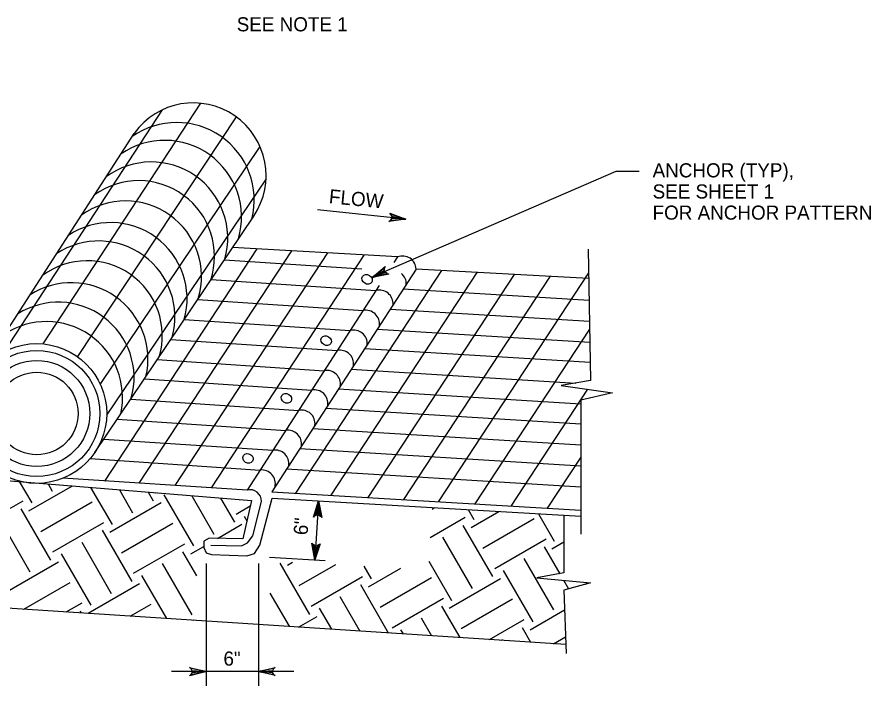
# Model space of a CAD drawing. Extents: x 636462 to 638208, y 299350 to 300538.
# Drawn here: x 636572.1 to 636753.7, y 299625.6 to 299768 of the extents above; entities that cross this region are included whole.
import ezdxf

# ---------------------------------------------------------------- set-up
doc = ezdxf.new("R2010")
doc.units = 0
doc.layers.add('Default', color=7, linetype='Continuous')

msp = doc.modelspace()

# ---------------------------------------------------------------- linework, layer by layer
at = {"layer": 'Default'}
for p, q in [((636577.62, 299698.4), (636611.18, 299749.62)), ((636602.95, 299748.21), (636569.31, 299696.75)), ((636618.69, 299746.73), (636584.88, 299695.7)), ((636563.74, 299691.65), (636596.98, 299743.21)), ((636589.76, 299689.79), (636623.74, 299740.43)), ((636647.45, 299712.59), (636699.52, 299735.16)), ((636699.52, 299735.16), (636704.42, 299735.16)), ((636625.02, 299733.53), (636591.11, 299683.2)), ((636588.59, 299675.29), (636622.41, 299725.61)), ((636623.04, 299718.61), (636590.67, 299669.22)), ((636630.4, 299718.19), (636597.99, 299668.75)), ((636638.07, 299717.76), (636605.62, 299668.25)), ((636653.02, 299716.91), (636617.9, 299718.9)), ((636645.85, 299717.32), (636613.36, 299667.75)), ((636616.16, 299716.31), (636645.39, 299714.35)), ((636662.37, 299714.01), (636631.31, 299666.62)), ((636669.89, 299713.61), (636638.8, 299666.18)), ((636677.82, 299713.19), (636646.7, 299665.71)), ((636685.43, 299712.79), (636654.27, 299665.25)), ((636693.62, 299713.56), (636661.67, 299664.81)), ((636613.32, 299712.09), (636648.39, 299709.74)), ((636649.11, 299710.86), (636621, 299667.25)), ((636654.22, 299710.11), (636693.73, 299707.71)), ((636610.48, 299707.86), (636645.66, 299705.5)), ((636651.42, 299705.79), (636693.81, 299703.21)), ((636607.62, 299703.61), (636642.91, 299701.24)), ((636648.64, 299701.51), (636693.89, 299698.75)), ((636693.84, 299701.52), (636669.47, 299664.35)), ((636604.77, 299699.36), (636640.17, 299696.98)), ((636646.02, 299697.45), (636693.97, 299694.53)), ((636601.89, 299695.08), (636637.4, 299692.69)), ((636643.12, 299692.99), (636690.93, 299690.08)), ((636599.13, 299690.98), (636634.75, 299688.58)), ((636640.42, 299688.82), (636691.97, 299685.68)), ((636693.42, 299688.76), (636677.13, 299663.89)), ((636596.23, 299686.66), (636631.96, 299684.26)), ((636637.75, 299684.7), (636691.97, 299681.4)), ((636593.35, 299682.38), (636629.2, 299679.97)), ((636634.97, 299680.41), (636691.97, 299676.94)), ((636590.52, 299678.16), (636626.47, 299675.75)), ((636632.19, 299676.12), (636691.97, 299672.48)), ((636691.97, 299674.29), (636684.85, 299663.43)), ((636587.6, 299673.98), (636623.77, 299671.55)), ((636629.37, 299671.78), (636691.97, 299667.96)), ((636572.53, 299669.11), (636575.17, 299664.54)), ((636578.65, 299668.61), (636579.54, 299667.07)), ((636621, 299667.25), (636581.82, 299669.8)), ((636574.58, 299662.85), (636583.82, 299668.18)), ((636587.7, 299667.86), (636592.27, 299659.96)), ((636593.82, 299667.36), (636596.63, 299662.48)), ((636599.93, 299666.86), (636601, 299665)), ((636562.4, 299658.73), (636573.32, 299665.03)), ((636601.46, 299666.72), (636601.47, 299666.73)), ((636603.27, 299666.31), (636609.57, 299655.39)), ((636609.22, 299666.09), (636613.94, 299657.91)), ((636615.33, 299665.59), (636618.31, 299660.43)), ((636636.18, 299664.97), (636635.43, 299652.42)), ((636572.86, 299663.31), (636579.17, 299652.39)), ((636577.11, 299658.48), (636588.02, 299664.79)), ((636591.76, 299658.31), (636602.68, 299664.62)), ((636618.64, 299662.18), (636621.65, 299663.92)), ((636660.34, 299663.26), (636660.82, 299663.54)), ((636620.36, 299661.72), (636620.94, 299660.72)), ((636659.97, 299657.23), (636667.38, 299661.5)), ((636668, 299663.12), (636669.22, 299661.01)), ((636668.64, 299659.32), (636674.57, 299662.74)), ((636682.95, 299662.26), (636686.32, 299656.43)), ((636568.5, 299660.79), (636574.8, 299649.87)), ((636579.63, 299654.12), (636590.54, 299660.42)), ((636594.28, 299653.94), (636605.2, 299660.25)), ((636614.71, 299657), (636619.9, 299660)), ((636666.92, 299659.78), (636673.22, 299648.86)), ((636671.16, 299654.95), (636682.08, 299661.25)), ((636590.17, 299658.75), (636596.47, 299647.83)), ((636585.8, 299656.22), (636592.1, 299645.3)), ((636596.8, 299649.58), (636607.72, 299655.88)), ((636662.55, 299657.26), (636668.85, 299646.34)), ((636673.68, 299650.58), (636684.6, 299656.89)), ((636685.81, 299654.78), (636688.34, 299656.24)), ((636607.26, 299654.16), (636610.23, 299649.01)), ((636608.99, 299653.7), (636611.77, 299655.31)), ((636684.22, 299655.21), (636687.52, 299649.49)), ((636581.43, 299653.7), (636587.73, 299642.78)), ((636625.77, 299653), (636637.61, 299652.29)), ((636679.85, 299652.69), (636686.16, 299641.77)), ((636569.92, 299645.71), (636580.84, 299652.01)), ((636602.9, 299651.64), (636609.2, 299640.72)), ((636612.26, 299651.65), (636612.26, 299625.6)), ((636623.44, 299651.65), (636623.44, 299625.6)), ((636627.98, 299651.76), (636634.29, 299640.84)), ((636629.58, 299651.33), (636630.66, 299651.95)), ((636632.1, 299646.96), (636639.88, 299651.45)), ((636645.82, 299651.12), (636647.39, 299648.4)), ((636646.8, 299646.71), (636653.69, 299650.69)), ((636659.66, 299652.17), (636664.48, 299643.82)), ((636598.53, 299649.12), (636603.82, 299639.95)), ((636634.62, 299642.59), (636645.54, 299648.89)), ((636649.32, 299642.34), (636660.24, 299648.65)), ((636675.48, 299650.17), (636681.79, 299639.25)), ((636688.34, 299650.41), (636688.34, 299650.41)), ((636573.47, 299641.93), (636583.37, 299647.64)), ((636587.15, 299641.09), (636598.07, 299647.39)), ((636645.08, 299647.17), (636651.02, 299636.88)), ((636663.98, 299642.17), (636674.9, 299648.48)), ((636688.33, 299648.08), (636689.37, 299646.29)), ((636693, 299647.28), (636693.57, 299647.61)), ((636625.85, 299645.36), (636629.92, 299638.32)), ((636582.53, 299641.34), (636585.89, 299643.27)), ((636640.71, 299644.65), (636644.97, 299637.27)), ((636651.84, 299637.98), (636662.76, 299644.28)), ((636666.5, 299637.8), (636677.42, 299644.11)), ((636585.43, 299641.55), (636585.67, 299641.13)), ((636596.13, 299640.45), (636600.59, 299643.03)), ((636636.34, 299642.13), (636638.92, 299637.67)), ((636662.38, 299642.61), (636666.26, 299635.89)), ((636681.2, 299637.56), (636688.5, 299641.77)), ((636609.57, 299639.58), (636609.74, 299639.68)), ((636631.93, 299638.12), (636635.88, 299640.41)), ((636658.01, 299640.08), (636660.21, 299636.28)), ((636672.56, 299635.48), (636679.94, 299639.74)), ((636679.48, 299638.02), (636681.27, 299634.91)), ((636653.65, 299637.56), (636654.16, 299636.68)), ((636686.15, 299634.59), (636688.72, 299636.08)), ((636675.11, 299635.5), (636675.22, 299635.3))]:
    msp.add_line(p, q, dxfattribs=at)
for points in [[(636654.73, 299724.96), (636635.99, 299726.96)], [(636651.59, 299725.97), (636651.35, 299726.23), (636654.73, 299724.96), (636651.59, 299725.97), (636651.74, 299725.58), (636654.73, 299724.96), (636651.69, 299725.06), (636651.47, 299724.71), (636654.73, 299724.96), (636651.16, 299724.49), (636651.47, 299724.71)], [(636693.52, 299718.59), (636694.04, 299690.59), (636687.82, 299689.56), (636698.71, 299688), (636691.97, 299686.45), (636691.97, 299657.93)], [(636653.02, 299716.91), (636652.24, 299715.7)], [(636693.64, 299712.35), (636656.94, 299714.3), (636626.23, 299666.93), (636691.97, 299663.01)], [(636650.77, 299713.37), (636651.11, 299713.28), (636647.57, 299712.57), (636650.77, 299713.37), (636650.43, 299713.62), (636647.57, 299712.57), (636650.2, 299714.09), (636650.21, 299714.51), (636647.57, 299712.57), (636650.35, 299714.86), (636650.21, 299714.51)], [(636688.78, 299634.42), (636554.58, 299643.16), (636554.06, 299670.63), (636621.9, 299665.05), (636620.1, 299656.88), (636612.91, 299657.04), (636611.77, 299656.39), (636611.77, 299655.08), (636612.26, 299653.94), (636613.4, 299653.61), (636620.92, 299653.29), (636622.55, 299653.78), (636623.69, 299655.57), (636626.31, 299665.54), (636691.97, 299661.73)], [(636635.36, 299661.78), (636635.12, 299661.52), (636636.18, 299664.97), (636635.36, 299661.78), (636635.74, 299661.95), (636636.18, 299664.97), (636636.26, 299661.93), (636636.63, 299661.72), (636636.18, 299664.97), (636636.87, 299661.43), (636636.63, 299661.72)], [(636613.24, 299655.57), (636619.77, 299655.41), (636621.08, 299656.06), (636622.22, 299657.53), (636624.02, 299664.88)], [(636688.34, 299661.94), (636688.34, 299649.64), (636682.64, 299648.6), (636694.04, 299647.56), (636688.34, 299646.01), (636688.86, 299632.53)], [(636636.28, 299655.6), (636636.52, 299655.86), (636635.43, 299652.42), (636636.28, 299655.6), (636635.9, 299655.43), (636635.43, 299652.42), (636635.38, 299655.46), (636635.01, 299655.67), (636635.43, 299652.42), (636634.78, 299655.97), (636635.01, 299655.67)], [(636623.44, 299628.65), (636604.94, 299628.65)], [(636609.03, 299629.28), (636608.76, 299629.51), (636612.26, 299628.65), (636609.03, 299629.28), (636609.22, 299628.91), (636612.26, 299628.65), (636609.23, 299628.39), (636609.05, 299628.01), (636612.26, 299628.65), (636608.77, 299627.76), (636609.05, 299628.01)], [(636626.67, 299628.01), (636626.94, 299627.79), (636623.44, 299628.65), (636626.67, 299628.01), (636626.47, 299628.38), (636623.44, 299628.65), (636626.46, 299628.91), (636626.65, 299629.28), (636623.44, 299628.65), (636626.93, 299629.54), (636626.65, 299629.28)], [(636630.92, 299628.65), (636623.44, 299628.65)]]:
    msp.add_lwpolyline(points, dxfattribs=at)
for radius in [14.88, 13.43, 11.28, 8.79]:
    msp.add_circle((636576.24, 299683.59), radius, dxfattribs=at)
for centre, radius, start, end in [((636609.57, 299734.24), 15.46, 326.0952, 144.5491), ((636606.01, 299729.05), 16.48, 345.6534, 124.9756), ((636603.46, 299725.37), 16.36, 343.691, 124.6206), ((636600.64, 299720.9), 16.23, 344.033, 126.3667), ((636597.94, 299717.03), 16.12, 341.7843, 125.5993), ((636595.16, 299712.71), 16.13, 343.2718, 125.615), ((636591.98, 299707.99), 16.24, 344.2854, 123.6551), ((636589.42, 299704.09), 16.22, 344.621, 123.4258), ((636586.99, 299700.16), 15.95, 343.6817, 126.5692), ((636654.05, 299714.22), 2.89, 1.5837, 111.0362), ((636651.96, 299711.2), 2.89, 357.4698, 49.2445), ((636583.61, 299695.16), 16.28, 346.883, 122.5672), ((636649.15, 299706.95), 2.89, 355.8364, 105.2889), ((636580.84, 299691.18), 16.11, 344.3862, 122.4125), ((636646.25, 299702.65), 2.91, 352.2758, 101.7284), ((636578.33, 299686.99), 16.16, 347.5648, 123.4971), ((636643.67, 299698.47), 2.88, 355.7866, 105.2391), ((636640.77, 299694.16), 2.89, 352.6221, 102.0746), ((636637.96, 299689.86), 2.89, 351.7367, 101.1893), ((636635.28, 299685.74), 2.89, 351.0209, 100.4735), ((636632.58, 299681.46), 2.86, 352.9967, 102.4492), ((636629.7, 299677.14), 2.88, 350.6196, 100.0721), ((636627, 299672.93), 2.87, 351.0283, 100.4809), ((636624.1, 299668.66), 2.91, 346.9651, 96.4176), ((636621.67, 299665), 2.35, 357.1849, 106.6375)]:
    msp.add_arc(centre, radius, start, end, dxfattribs=at)
for centre in [(636646.53, 299712.15), (636637.81, 299699.08), (636629.36, 299686.82), (636621.19, 299674.02)]:
    msp.add_ellipse(centre, major_axis=(0.973, -0.608), ratio=0.861411, dxfattribs=at)

# ---------------------------------------------------------------- texts
for s, p in [('SEE NOTE 1', (636618.78, 299764.93)), ('ANCHOR (TYP),', (636707.26, 299733.85)), ('SEE SHEET 1', (636707.26, 299729.35)), ('FOR ANCHOR PATTERN', (636707.26, 299724.85)), ('6"', (636615.96, 299629.93))]:
    msp.add_text(s, height=2.998, dxfattribs=at).set_placement(p)
for s, rotation, p in [('FLOW', 354.4427, (636638.3, 299728.36)), ('6"', 85.0729, (636633.83, 299657.61))]:
    msp.add_text(s, height=2.998, rotation=rotation, dxfattribs=at).set_placement(p)

doc.saveas('drawing.dxf')
